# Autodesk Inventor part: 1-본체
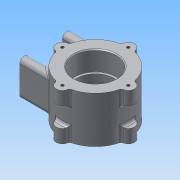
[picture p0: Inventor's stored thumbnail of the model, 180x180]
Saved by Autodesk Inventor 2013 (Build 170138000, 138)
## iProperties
Created: 2015-03
Part Number: 1-본체
Material: 알루미늄 6061
Document SubType Name: Modeling
Designer: ST3
Density: 2.71 g/cm^3
Mass: 455.721 g
Surface Area: 336.677 cm^2
Volume: 168.163 cm^3
Author: ST3
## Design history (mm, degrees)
sketch "스케치1"
  geometry: C1 r 37 at (0, 0); 1 further point
  constraints: 1 centre point, 1 coincident
  dimensions: "d0" = 74 diameter of C1
extrude "돌출1" new body sketch "스케치1" distance "d2" = 52; taper "d3" = 0 deg
sketch "스케치2"
  geometry: C1 r 37 at (0, 0) reference; C2 r 23.5 at (0, 0)
  constraints: 1 centre point, 1 coincident
  dimensions: "d4" = 47 diameter of C2
extrude "돌출2" cut sketch "스케치2" distance "d6" = 22; taper "d7" = 0 deg
sketch "스케치3"
  geometry: C1 r 37 at (0, 0) reference; C2 r 23.5 at (0, 0)
  constraints: 1 centre point, 1 coincident
  dimensions: "d8" = 47 diameter of C2
extrude "돌출3" cut sketch "스케치3" distance "d11" = 22; taper "d12" = 0 deg
sketch "스케치4"
  geometry: C1 r 23.5 at (0, 0) reference; C2 r 21 at (0, 0)
  constraints: 1 centre point, 1 coincident
  dimensions: "d13" = 42 diameter of C2
extrude "돌출4" cut sketch "스케치4" stored distance "d15" = 22; taper "d16" = 0 deg
node "작업 평면2"
sketch "스케치6"
  geometry: L1 (-29, 11)-(-29, 41); L2 (-19, 41)-(-19, 11); L3 (19, 11)-(19, 41); L4 (29, 41)-(29, 11); L5 (-37, 0)-(37, 0) reference; L6 (37, 52)-(-37, 52) reference; L7 (0, 0)-(0, 52); L8 (-37, 0)-(-37, 52) reference; L9 (37, 0)-(37, 52) reference; L10 (-37, 26)-(37, 26); A1 r 5 centre (-24, 41) between (-19, 41) and (-29, 41); A2 r 5 centre (-24, 11) between (-29, 11) and (-19, 11); A3 r 5 centre (24, 41) between (29, 41) and (19, 41); A4 r 5 centre (24, 11) between (19, 11) and (29, 11)
  constraints: 12 end point, 8 point on circle, 8 tangent, 4 centre point, 3 midpoint, 3 parallel, 1 vertical
  dimensions: "d18" = 10 distance between parallel lines of L4 L3; "d20" = 10 distance between parallel lines of L2 L1; "d21" = 24 distance from line of L7 A1.centre; "d22" = 24 distance from line of L7 A3.centre; "d23" = 40 dimension on A1 A2; "d24" = 40 dimension on A3 A4; "d25" = 20 dimension on A2 L10; "d26" = 20 dimension on A4 L10
extrude "돌출5" join sketch "스케치6" stored distance "d27" = 22; taper "d28" = 0 deg
sketch "스케치7"
  geometry: C1 r 2.5 at (11, 24); C2 r 2.5 at (41, 24); A1 r 5 centre (41, 24) between (41, 19) and (41, 29) reference; A2 r 5 centre (11, 24) between (11, 29) and (11, 19) reference; 1 further point
  constraints: 2 centre point, 2 coincident
  dimensions: "d29" = 5 diameter of C2; "d32" = 5 diameter of C1
hole "구멍1" sketch "스케치7" at (11, 24), (41, 24) diameter "d33" = 4.134; stored, may be unused: countersink angle "d37" = 90 deg, drill point angle "d39" = 118 deg; dims "d34" = 6, "d35" = 4, "d36" = 2, "d38" = 8
sketch "스케치8"
  geometry: A1 r 5 centre (41, -24) between (41, -29) and (41, -19) reference; A2 r 5 centre (11, -24) between (11, -19) and (11, -29) reference; 1 further point
hole "구멍2" sketch "스케치8" at (11, -24), (41, -24) diameter "d40" = 4.134; stored, may be unused: countersink angle "d44" = 90 deg, drill point angle "d46" = 118 deg; dims "d41" = 6, "d42" = 4, "d43" = 2, "d45" = 8
sketch "스케치9"
  geometry: L1 (-37, 0)-(37, 0); L2 (0, -37)-(0, 37); C1 r 23.5 at (0, 0) reference; A1 r 37 centre (0, 0) between (-37, 0) and (37, 0) reference; A2 r 7 centre (-37, 0) between (-36.338, 6.969) and (-36.338, -6.969)
  constraints: 8 point on circle, 4 end point, 1 centre point, 1 coincident, 1 horizontal, 1 perpendicular
  dimensions: "d47" = 0 distance from line of C1.centre L1; "d48" = 0 distance from line of C1.centre L2; "d49" = 14 diameter of A2
extrude "돌출6" join sketch "스케치9" distance "d50" = 15; taper "d51" = 0 deg
sketch "스케치10"
  geometry: L1 (0, 0)-(37, 0); A1 r 37 centre (0, 0) between (37, 0) and (36.338, -6.969) reference; A2 r 7 centre (37, 0) between (36.338, -6.969) and (36.338, 6.969)
  constraints: 5 point on circle, 2 end point, 1 centre point, 1 coincident, 1 horizontal
  dimensions: "d55" = 14 diameter of A2
extrude "돌출7" join sketch "스케치10" distance "d57" = 15; taper "d58" = 0 deg
sketch "스케치11"
  geometry: A1 r 7 centre (0, 37) between (6.969, 36.338) and (-6.969, 36.338) reference; A2 r 7 centre (-37, 0) between (-36.338, 6.969) and (-36.338, -6.969) reference; A3 r 7 centre (0, -37) between (-6.969, -36.338) and (6.969, -36.338) reference; A4 r 7 centre (37, 0) between (36.338, -6.969) and (36.338, 6.969) reference
hole "구멍3" sketch "스케치11" at (37, 0), (0, 37), (0, -37), (-37, 0) diameter "d62" = 3.242; stored, may be unused: countersink angle "d66" = 90 deg, drill point angle "d68" = 118 deg; dims "d63" = 8, "d64" = 4, "d65" = 2, "d67" = 11
sketch "스케치12"
  geometry: A1 r 7 centre (0, -37) between (-6.969, -36.338) and (6.969, -36.338) reference; A2 r 7 centre (37, 0) between (36.338, -6.969) and (36.338, 6.969) reference; A3 r 7 centre (0, 37) between (6.969, 36.338) and (-6.969, 36.338) reference; A4 r 7 centre (-37, 0) between (-36.338, 6.969) and (-36.338, -6.969) reference
hole "구멍4" sketch "스케치12" at (-37, 0), (0, -37), (37, 0), (0, 37) diameter "d69" = 3.242; stored, may be unused: countersink angle "d73" = 90 deg, drill point angle "d75" = 118 deg; dims "d70" = 8, "d71" = 4, "d72" = 2, "d74" = 11
fillet "모깎기1" dims "d76" = 3
fillet "모깎기2" dims "d80" = 3
chamfer "모따기1" distance "d84" = 1; stored, may be unused: second distance "d85" = 2, angle "d86" = 45 deg
chamfer "모따기2" distance "d87" = 1; stored, may be unused: second distance "d88" = 2, angle "d89" = 45 deg
fillet "모깎기3" dims "d90" = 3
fillet "모깎기4" dims "d92" = 0.3
node "솔리드1"
pattern_circular "원형 패턴1" dims angle "d53" = 360 deg
pattern_circular "원형 패턴2" dims angle "d60" = 360 deg
pattern_circular "원형 패턴3" dims angle "d78" = 360 deg
pattern_circular "원형 패턴4" dims angle "d82" = 360 deg
other parameters: "d17" = -56
